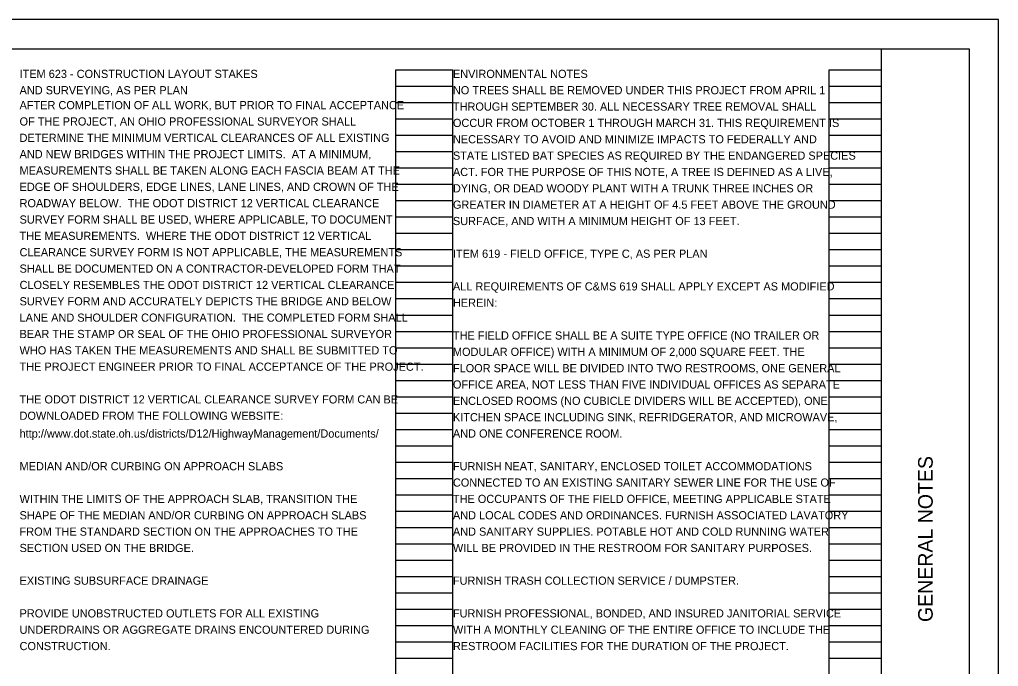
# Model space of a CAD drawing. Extents: x 0 to 74, y -27.6 to 51.8.
# Drawn here: x 17.24 to 34, y 10.92 to 22 of the extents above; entities that cross this region are included whole.
import ezdxf

# ---------------------------------------------------------------- set-up
doc = ezdxf.new("R2010")
doc.units = 0
for name, color, linetype in [('Level 1', 7, 'Continuous'), ('Level 2', 7, 'Continuous'), ('Level 3', 7, 'Continuous'), ('Level 4', 7, 'Continuous')]:
    doc.layers.add(name, color=color, linetype=linetype)

msp = doc.modelspace()

# ---------------------------------------------------------------- linework, layer by layer
at = {"layer": 'Level 1'}
msp.add_lwpolyline([(0, 0), (34, 0), (34, 22), (0, 22)], close=True, dxfattribs=at)
at = {"layer": 'Level 2'}
msp.add_line((32, 0.5), (32, 21.5), dxfattribs=at)
msp.add_lwpolyline([(1.5, 21.5), (33.5, 21.5), (33.5, 0.5), (1.5, 0.5)], close=True, dxfattribs=at)
at = {"layer": 'Level 3'}
for p, q in [((23.68, 0.98), (23.68, 21.14)), ((23.68, 21.14), (24.66, 21.14)), ((24.66, 0.98), (24.66, 21.14)), ((31.1, 0.98), (31.1, 21.14)), ((31.1, 21.14), (32, 21.14)), ((32, 0.98), (32, 21.14)), ((23.68, 20.86), (24.66, 20.86)), ((31.1, 20.86), (32, 20.86)), ((23.68, 20.58), (24.66, 20.58)), ((31.1, 20.58), (32, 20.58)), ((23.68, 20.3), (24.66, 20.3)), ((31.1, 20.3), (32, 20.3)), ((23.68, 20.02), (24.66, 20.02)), ((31.1, 20.02), (32, 20.02)), ((23.68, 19.74), (24.66, 19.74)), ((31.1, 19.74), (32, 19.74)), ((23.68, 19.46), (24.66, 19.46)), ((31.1, 19.46), (32, 19.46)), ((23.68, 19.18), (24.66, 19.18)), ((31.1, 19.18), (32, 19.18)), ((23.68, 18.9), (24.66, 18.9)), ((31.1, 18.9), (32, 18.9)), ((23.68, 18.62), (24.66, 18.62)), ((31.1, 18.62), (32, 18.62)), ((23.68, 18.34), (24.66, 18.34)), ((31.1, 18.34), (32, 18.34)), ((23.68, 18.06), (24.66, 18.06)), ((31.1, 18.06), (32, 18.06)), ((23.68, 17.78), (24.66, 17.78)), ((31.1, 17.78), (32, 17.78)), ((23.68, 17.5), (24.66, 17.5)), ((31.1, 17.5), (32, 17.5)), ((23.68, 17.22), (24.66, 17.22)), ((31.1, 17.22), (32, 17.22)), ((23.68, 16.94), (24.66, 16.94)), ((31.1, 16.94), (32, 16.94)), ((23.68, 16.66), (24.66, 16.66)), ((31.1, 16.66), (32, 16.66)), ((23.68, 16.38), (24.66, 16.38)), ((31.1, 16.38), (32, 16.38)), ((23.68, 16.1), (24.66, 16.1)), ((31.1, 16.1), (32, 16.1)), ((23.68, 15.82), (24.66, 15.82)), ((31.1, 15.82), (32, 15.82)), ((23.68, 15.54), (24.66, 15.54)), ((31.1, 15.54), (32, 15.54)), ((23.68, 15.26), (24.66, 15.26)), ((31.1, 15.26), (32, 15.26)), ((23.68, 14.98), (24.66, 14.98)), ((31.1, 14.98), (32, 14.98)), ((23.68, 14.7), (24.66, 14.7)), ((31.1, 14.7), (32, 14.7)), ((23.68, 14.42), (24.66, 14.42)), ((31.1, 14.42), (32, 14.42)), ((23.68, 14.14), (24.66, 14.14)), ((31.1, 14.14), (32, 14.14)), ((23.68, 13.86), (24.66, 13.86)), ((31.1, 13.86), (32, 13.86)), ((23.68, 13.58), (24.66, 13.58)), ((31.1, 13.58), (32, 13.58)), ((23.68, 13.3), (24.66, 13.3)), ((31.1, 13.3), (32, 13.3)), ((23.68, 13.02), (24.66, 13.02)), ((31.1, 13.02), (32, 13.02)), ((23.68, 12.74), (24.66, 12.74)), ((31.1, 12.74), (32, 12.74)), ((23.68, 12.46), (24.66, 12.46)), ((31.1, 12.46), (32, 12.46)), ((23.68, 12.18), (24.66, 12.18)), ((31.1, 12.18), (32, 12.18)), ((23.68, 11.9), (24.66, 11.9)), ((31.1, 11.9), (32, 11.9)), ((23.68, 11.62), (24.66, 11.62)), ((31.1, 11.62), (32, 11.62)), ((23.68, 11.34), (24.66, 11.34)), ((31.1, 11.34), (32, 11.34)), ((23.68, 11.06), (24.66, 11.06)), ((31.1, 11.06), (32, 11.06))]:
    msp.add_line(p, q, dxfattribs=at)

# ---------------------------------------------------------------- texts
msp.add_text('GENERAL NOTES', height=0.25, rotation=90, dxfattribs=at).set_placement((32.875, 11.682))
at = {"layer": 'Level 4'}
for s, p in [('ITEM 623 - CONSTRUCTION LAYOUT STAKES ', (17.24, 21)), ('ENVIRONMENTAL NOTES', (24.66, 21)), ('AND SURVEYING, AS PER PLAN', (17.24, 20.72)), ('NO TREES SHALL BE REMOVED UNDER THIS PROJECT FROM APRIL 1 ', (24.66, 20.72)), ('AFTER COMPLETION OF ALL WORK, BUT PRIOR TO FINAL ACCEPTANCE ', (17.24, 20.465)), ('THROUGH SEPTEMBER 30. ALL NECESSARY TREE REMOVAL SHALL ', (24.66, 20.44)), ('OF THE PROJECT, AN OHIO PROFESSIONAL SURVEYOR SHALL ', (17.24, 20.185)), ('OCCUR FROM OCTOBER 1 THROUGH MARCH 31. THIS REQUIREMENT IS ', (24.66, 20.16)), ('DETERMINE THE MINIMUM VERTICAL CLEARANCES OF ALL EXISTING ', (17.24, 19.905)), ('NECESSARY TO AVOID AND MINIMIZE IMPACTS TO FEDERALLY AND ', (24.66, 19.88)), ('AND NEW BRIDGES WITHIN THE PROJECT LIMITS.  AT A MINIMUM, ', (17.24, 19.625)), ('STATE LISTED BAT SPECIES AS REQUIRED BY THE ENDANGERED SPECIES ', (24.66, 19.6)), ('MEASUREMENTS SHALL BE TAKEN ALONG EACH FASCIA BEAM AT THE ', (17.24, 19.345)), ('ACT. FOR THE PURPOSE OF THIS NOTE, A TREE IS DEFINED AS A LIVE, ', (24.66, 19.32)), ('EDGE OF SHOULDERS, EDGE LINES, LANE LINES, AND CROWN OF THE ', (17.24, 19.065)), ('DYING, OR DEAD WOODY PLANT WITH A TRUNK THREE INCHES OR ', (24.66, 19.04)), ('ROADWAY BELOW.  THE ODOT DISTRICT 12 VERTICAL CLEARANCE ', (17.24, 18.785)), ('GREATER IN DIAMETER AT A HEIGHT OF 4.5 FEET ABOVE THE GROUND ', (24.66, 18.76)), ('SURVEY FORM SHALL BE USED, WHERE APPLICABLE, TO DOCUMENT ', (17.24, 18.505)), ('SURFACE, AND WITH A MINIMUM HEIGHT OF 13 FEET.', (24.66, 18.48)), ('THE MEASUREMENTS.  WHERE THE ODOT DISTRICT 12 VERTICAL ', (17.24, 18.225)), ('CLEARANCE SURVEY FORM IS NOT APPLICABLE, THE MEASUREMENTS ', (17.24, 17.945)), ('ITEM 619 - FIELD OFFICE, TYPE C, AS PER PLAN', (24.66, 17.92)), ('SHALL BE DOCUMENTED ON A CONTRACTOR-DEVELOPED FORM THAT ', (17.24, 17.665)), ('CLOSELY RESEMBLES THE ODOT DISTRICT 12 VERTICAL CLEARANCE ', (17.24, 17.385)), ('ALL REQUIREMENTS OF C&MS 619 SHALL APPLY EXCEPT AS MODIFIED ', (24.66, 17.36)), ('SURVEY FORM AND ACCURATELY DEPICTS THE BRIDGE AND BELOW ', (17.24, 17.105)), ('HEREIN:', (24.66, 17.08)), ('LANE AND SHOULDER CONFIGURATION.  THE COMPLETED FORM SHALL ', (17.24, 16.825)), ('BEAR THE STAMP OR SEAL OF THE OHIO PROFESSIONAL SURVEYOR ', (17.24, 16.545)), ('THE FIELD OFFICE SHALL BE A SUITE TYPE OFFICE (NO TRAILER OR ', (24.66, 16.52)), ('WHO HAS TAKEN THE MEASUREMENTS AND SHALL BE SUBMITTED TO ', (17.24, 16.265)), ('MODULAR OFFICE) WITH A MINIMUM OF 2,000 SQUARE FEET. THE ', (24.66, 16.24)), ('THE PROJECT ENGINEER PRIOR TO FINAL ACCEPTANCE OF THE PROJECT.', (17.24, 15.985)), ('FLOOR SPACE WILL BE DIVIDED INTO TWO RESTROOMS, ONE GENERAL ', (24.66, 15.96)), ('OFFICE AREA, NOT LESS THAN FIVE INDIVIDUAL OFFICES AS SEPARATE ', (24.66, 15.68)), ('THE ODOT DISTRICT 12 VERTICAL CLEARANCE SURVEY FORM CAN BE ', (17.24, 15.425)), ('ENCLOSED ROOMS (NO CUBICLE DIVIDERS WILL BE ACCEPTED), ONE ', (24.66, 15.4)), ('DOWNLOADED FROM THE FOLLOWING WEBSITE:', (17.24, 15.145)), ('KITCHEN SPACE INCLUDING SINK, REFRIDGERATOR, AND MICROWAVE, ', (24.66, 15.12)), ('http://www.dot.state.oh.us/districts/D12/HighwayManagement/Documents/', (17.24, 14.84)), ('AND ONE CONFERENCE ROOM.', (24.66, 14.84)), ('MEDIAN AND/OR CURBING ON APPROACH SLABS', (17.24, 14.28)), ('FURNISH NEAT, SANITARY, ENCLOSED TOILET ACCOMMODATIONS ', (24.66, 14.28)), ('CONNECTED TO AN EXISTING SANITARY SEWER LINE FOR THE USE OF ', (24.66, 14)), ('WITHIN THE LIMITS OF THE APPROACH SLAB, TRANSITION THE', (17.24, 13.72)), ('THE OCCUPANTS OF THE FIELD OFFICE, MEETING APPLICABLE STATE ', (24.66, 13.72)), ('SHAPE OF THE MEDIAN AND/OR CURBING ON APPROACH SLABS', (17.24, 13.44)), ('AND LOCAL CODES AND ORDINANCES. FURNISH ASSOCIATED LAVATORY ', (24.66, 13.44)), ('FROM THE STANDARD SECTION ON THE APPROACHES TO THE', (17.24, 13.16)), ('AND SANITARY SUPPLIES. POTABLE HOT AND COLD RUNNING WATER ', (24.66, 13.16)), ('SECTION USED ON THE BRIDGE.', (17.24, 12.88)), ('WILL BE PROVIDED IN THE RESTROOM FOR SANITARY PURPOSES.', (24.66, 12.88)), ('EXISTING SUBSURFACE DRAINAGE', (17.24, 12.32)), ('FURNISH TRASH COLLECTION SERVICE / DUMPSTER.', (24.66, 12.32)), ('PROVIDE UNOBSTRUCTED OUTLETS FOR ALL EXISTING', (17.24, 11.76)), ('FURNISH PROFESSIONAL, BONDED, AND INSURED JANITORIAL SERVICE ', (24.66, 11.76)), ('UNDERDRAINS OR AGGREGATE DRAINS ENCOUNTERED DURING', (17.24, 11.48)), ('WITH A MONTHLY CLEANING OF THE ENTIRE OFFICE TO INCLUDE THE ', (24.66, 11.48)), ('CONSTRUCTION.', (17.24, 11.2)), ('RESTROOM FACILITIES FOR THE DURATION OF THE PROJECT.', (24.66, 11.2))]:
    msp.add_text(s, height=0.14, dxfattribs=at).set_placement(p)

doc.saveas('drawing.dxf')
